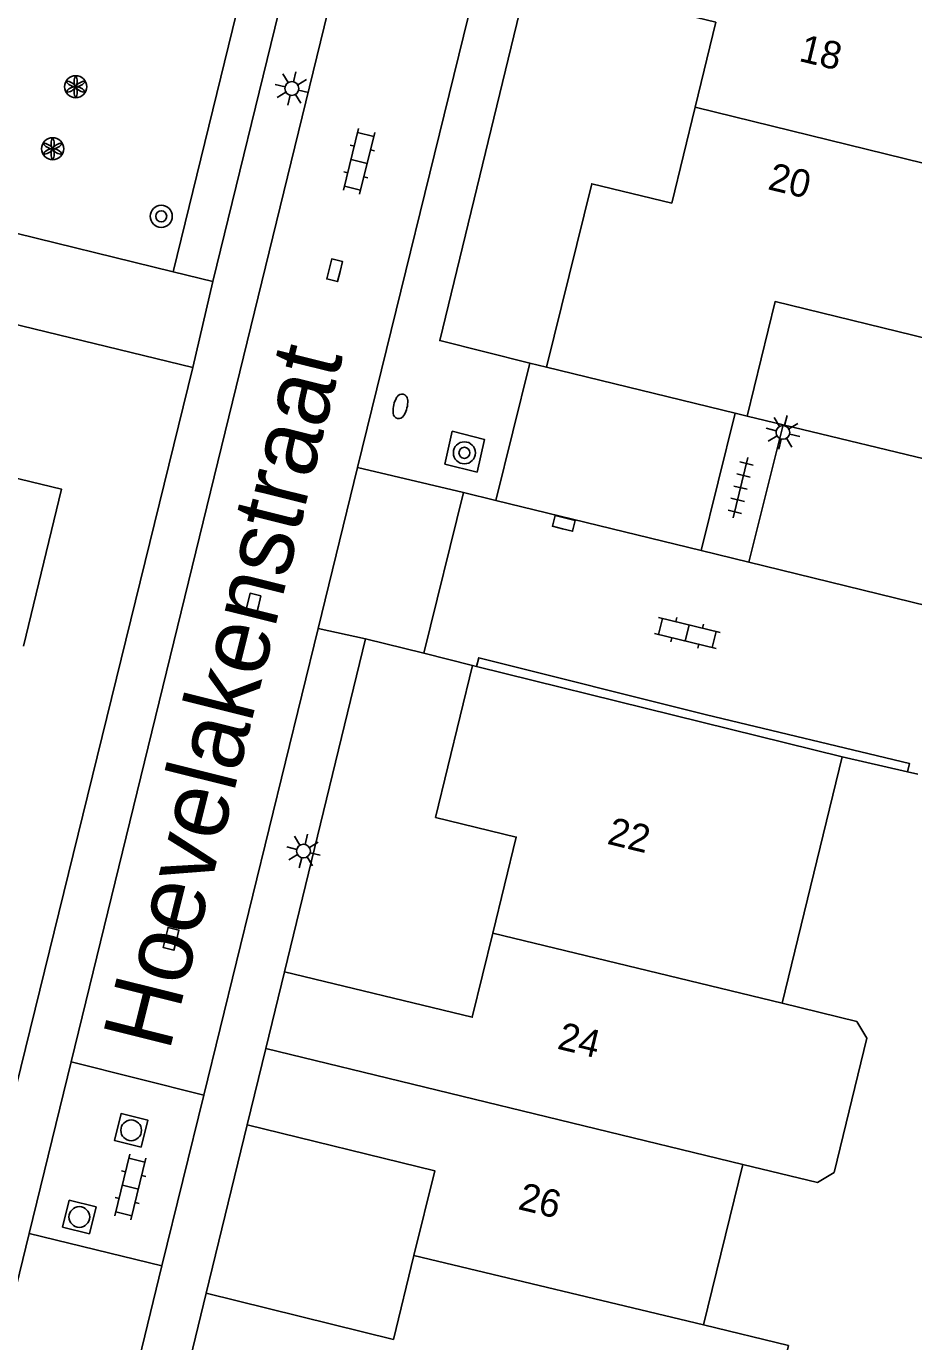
# Model space of a CAD drawing. Extents: x 128000 to 131008, y 398996 to 402500.
# Drawn here: x 128188.47 to 128220.62, y 399514.1 to 399561.75 of the extents above; entities that cross this region are included whole.
import ezdxf

# ---------------------------------------------------------------- set-up
doc = ezdxf.new("R2010")
doc.units = 0
for name, color, linetype in [('gg-afsc-hekwerk', 7, 'Continuous'), ('gg-afsc-muur', 7, 'Continuous'), ('gg-anno-huisnummerreeks BGT', 7, 'Continuous'), ('gg-anno-openbare ruimte label', 7, 'Continuous'), ('gg-bbg-gedigitaliseerde bebouwing', 7, 'Continuous'), ('gg-bbg-hoofdgebouw', 7, 'Continuous'), ('gg-bbg-tussenscheiding', 7, 'Continuous'), ('gg-knt-verharding', 7, 'Continuous'), ('gg-knt-verharding nz', 7, 'Continuous'), ('gt-grn-weggrens', 7, 'Continuous'), ('gt-symb-boom', 7, 'Continuous'), ('gt-symb-brandkraan', 7, 'Continuous'), ('gt-symb-klinker verharding', 7, 'Continuous'), ('gt-symb-kolk', 7, 'Continuous'), ('gt-symb-lichtmast', 7, 'Continuous'), ('gt-symb-rioolschacht', 7, 'Continuous'), ('gt-symb-solitaire heester', 7, 'Continuous'), ('gt-symb-tegel verharding', 7, 'Continuous')]:
    doc.layers.add(name, color=color, linetype=linetype)

# ---------------------------------------------------------------- blocks, each defined once
blk = doc.blocks.new('gt0-KOLK')
at = {"layer": 'gt-symb-kolk'}
blk.add_lwpolyline([(0, 0), (0.375, 0), (0.375, 0.4), (-0.375, 0.4), (-0.375, 0), (0, 0)], dxfattribs=at)
blk = doc.blocks.new('gt0-TEG1')
at = {"layer": 'gt-symb-tegel verharding'}
for p, q in [((-1.125, 0), (1.125, 0)), ((-0.9, -0.25), (-0.9, 0.25)), ((-0.45, -0.25), (-0.45, 0.25)), ((0, -0.25), (0, 0.25)), ((0.45, -0.25), (0.45, 0.25)), ((0.9, -0.25), (0.9, 0.25))]:
    blk.add_line(p, q, dxfattribs=at)
blk = doc.blocks.new('gt0-LMAST')
at = {"layer": 'gt-symb-lichtmast'}
for p, q in [((-0.005, 0.246), (-0.005, 0.621)), ((-0.182, 0.173), (-0.447, 0.438)), ((0.172, 0.173), (0.437, 0.438)), ((-0.255, -0.004), (-0.63, -0.004)), ((-0.182, -0.181), (-0.447, -0.446)), ((-0.005, -0.254), (-0.005, -0.629)), ((0.437, -0.446), (0.172, -0.181)), ((0.245, -0.004), (0.62, -0.004))]:
    blk.add_line(p, q, dxfattribs=at)
blk.add_circle((-0.005, -0.004), 0.25, dxfattribs=at)
blk = doc.blocks.new('gt0-KL1')
at = {"layer": 'gt-symb-klinker verharding'}
for p, q in [((-1.15, 0.3), (1.15, 0.3)), ((-1, -0.3), (-1, 0.3)), ((-0.5, 0.3), (-0.5, 0.45)), ((0, -0.3), (0, 0.3)), ((0.5, 0.3), (0.5, 0.45)), ((1, -0.3), (1, 0.3)), ((-1.15, -0.3), (1.15, -0.3)), ((-0.5, -0.45), (-0.5, -0.3)), ((0.5, -0.45), (0.5, -0.3))]:
    blk.add_line(p, q, dxfattribs=at)
blk = doc.blocks.new('gt0-BR')
at = {"layer": 'gt-symb-brandkraan'}
for centre, radius, start, end in [((-0.244, 0), 0.206, 107.5669, 252.4331), ((0.599, -2.664), 3, 106.892, 107.5669), ((0, -0.691), 0.938, 73.108, 106.892), ((-0.599, -2.664), 3, 72.4331, 73.108), ((0.244, 0), 0.206, 287.567, 72.4331), ((0.599, 2.664), 3, 252.4331, 253.108), ((0, 0.691), 0.938, 253.108, 286.8921), ((-0.599, 2.664), 3, 286.8921, 287.567)]:
    blk.add_arc(centre, radius, start, end, dxfattribs=at)
blk = doc.blocks.new('gt0-BOOM')
at = {"layer": 'gt-symb-boom'}
for radius in [0.4, 0.2]:
    blk.add_circle((0, 0), radius, dxfattribs=at)
blk = doc.blocks.new('gt0-SH')
at = {"layer": 'gt-symb-solitaire heester'}
blk.add_circle((0, 0), 0.4, dxfattribs=at)
for centre, start, end in [((-0.346, 0.2), 270, 30), ((-0.346, -0.2), 330, 90), ((0, 0.4), 210, 330), ((0.346, 0.2), 150, 270), ((0.346, -0.2), 90, 210), ((0, -0.4), 30, 150)]:
    blk.add_arc(centre, 0.4, start, end, dxfattribs=at)
blk = doc.blocks.new('gt0-RS')
at = {"layer": 'gt-symb-rioolschacht'}
blk.add_lwpolyline([(-0.5, -0.5), (0.5, -0.5), (0.5, 0.5), (-0.5, 0.5)], close=True, dxfattribs=at)
blk.add_circle((0, 0), 0.375, dxfattribs=at)

msp = doc.modelspace()

# ---------------------------------------------------------------- linework, layer by layer
at = {"layer": 'gg-afsc-hekwerk'}
for p, q in [((128203.453, 399592.417), (128193.793, 399552.859)), ((128193.793, 399552.859), (128181.326, 399555.921))]:
    msp.add_line(p, q, dxfattribs=at)
at = {"layer": 'gg-afsc-muur'}
for p, q in [((128218.032, 399535.289), (128220.403, 399534.741)), ((128220.403, 399534.741), (128220.773, 399534.656))]:
    msp.add_line(p, q, dxfattribs=at)
at = {"layer": 'gg-bbg-gedigitaliseerde bebouwing'}
for p, q in [((128218.032, 399535.289), (128215.854, 399526.359)), ((128214.43, 399520.521), (128213.012, 399514.704))]:
    msp.add_line(p, q, dxfattribs=at)
for points in [[(128215.854, 399526.359), (128218.56, 399525.702), (128218.927, 399525.098), (128217.745, 399520.231), (128217.141, 399519.863), (128214.43, 399520.521)], [(128213.012, 399514.704), (128216.086, 399513.957), (128214.667, 399508.119), (128211.588, 399508.867)]]:
    msp.add_lwpolyline(points, dxfattribs=at)
at = {"layer": 'gg-bbg-hoofdgebouw'}
for p, q in [((128207.32, 399549.4), (128214.161, 399547.735)), ((128214.161, 399547.735), (128214.591, 399547.63)), ((128204.787, 399538.564), (128204.64, 399538.6)), ((128211.92, 399536.8), (128204.787, 399538.564)), ((128211.92, 399536.8), (128218.032, 399535.289)), ((128197.83, 399527.501), (128197.149, 399524.722)), ((128197.149, 399524.722), (128196.47, 399521.95)), ((128194.99, 399515.85), (128194.305, 399513.065))]:
    msp.add_line(p, q, dxfattribs=at)
for points in [[(128212.703, 399558.823), (128213.45, 399561.9), (128206.66, 399563.56)], [(128207.32, 399549.4), (128208.96, 399556.05), (128211.86, 399555.35), (128212.703, 399558.823)], [(128223.189, 399556.244), (128221.73, 399550.281), (128215.6, 399551.78), (128214.591, 399547.63)], [(128188.367, 399539.296), (128189.75, 399544.98), (128185.992, 399545.895)], [(128204.64, 399538.6), (128203.3, 399533.09), (128206.22, 399532.38), (128205.374, 399528.904)], [(128205.374, 399528.904), (128204.63, 399525.85), (128197.83, 399527.501)], [(128196.47, 399521.95), (128203.27, 399520.29), (128202.517, 399517.224)], [(128202.517, 399517.224), (128201.77, 399514.181), (128194.99, 399515.85)]]:
    msp.add_lwpolyline(points, dxfattribs=at)
at = {"layer": 'gg-bbg-tussenscheiding'}
for p, q in [((128212.703, 399558.823), (128223.189, 399556.244)), ((128205.374, 399528.904), (128215.854, 399526.359)), ((128197.149, 399524.722), (128214.43, 399520.521)), ((128202.517, 399517.224), (128213.012, 399514.704))]:
    msp.add_line(p, q, dxfattribs=at)
at = {"layer": 'gg-knt-verharding'}
for p, q in [((128205.008, 399592.472), (128195.231, 399552.506)), ((128190.091, 399524.233), (128201.678, 399571.644)), ((128200.476, 399545.767), (128206.527, 399570.454)), ((128195.231, 399552.506), (128193.793, 399552.859)), ((128194.5, 399549.39), (128185.888, 399551.491)), ((128194.5, 399549.39), (128176.7, 399476.98)), ((128205.486, 399544.573), (128206.715, 399549.552)), ((128206.715, 399549.552), (128207.32, 399549.4)), ((128214.161, 399547.735), (128212.919, 399542.758)), ((128215.897, 399547.315), (128214.591, 399547.63)), ((128214.656, 399542.334), (128215.897, 399547.315)), ((128223.442, 399545.498), (128215.897, 399547.315)), ((128199.046, 399539.934), (128200.476, 399545.767)), ((128202.87, 399539.038), (128204.31, 399544.86)), ((128204.31, 399544.86), (128205.486, 399544.573)), ((128212.919, 399542.758), (128214.656, 399542.334)), ((128194.901, 399523.025), (128199.046, 399539.934)), ((128200.76, 399539.56), (128197.83, 399527.501)), ((128202.87, 399539.038), (128200.76, 399539.56)), ((128204.64, 399538.6), (128202.87, 399539.038)), ((128188.573, 399518.02), (128190.091, 399524.233)), ((128190.091, 399524.233), (128194.901, 399523.025)), ((128193.385, 399516.842), (128194.901, 399523.025)), ((128196.47, 399521.95), (128194.99, 399515.85)), ((128178.59, 399477.177), (128188.573, 399518.02)), ((128193.385, 399516.842), (128188.573, 399518.02)), ((128183.37, 399475.983), (128193.385, 399516.842))]:
    msp.add_line(p, q, dxfattribs=at)
for points in [[(128206.66, 399563.56), (128203.45, 399550.37), (128206.715, 399549.552)], [(128204.801, 399545.606), (128203.636, 399545.896), (128203.901, 399547.084), (128205.07, 399546.788), (128204.801, 399545.606)], [(128220.403, 399534.741), (128220.475, 399535.04), (128213.115, 399536.811), (128204.865, 399538.876), (128204.787, 399538.564)]]:
    msp.add_lwpolyline(points, dxfattribs=at)
at = {"layer": 'gg-knt-verharding nz'}
for p, q in [((128205.486, 399544.573), (128212.919, 399542.758)), ((128214.656, 399542.334), (128222.199, 399540.493))]:
    msp.add_line(p, q, dxfattribs=at)
at = {"layer": 'gt-grn-weggrens'}
for p, q in [((128195.231, 399552.506), (128194.5, 399549.39)), ((128200.476, 399545.767), (128204.31, 399544.86)), ((128200.76, 399539.56), (128199.046, 399539.934))]:
    msp.add_line(p, q, dxfattribs=at)

# ---------------------------------------------------------------- block references
at = {"layer": 'gt-symb-boom', "rotation": -13.716469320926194}
msp.add_blockref('gt0-BOOM', (128193.358, 399554.87), dxfattribs=at)
at = {"layer": 'gt-symb-boom'}
msp.add_blockref('gt0-BOOM', (128204.345, 399546.301), dxfattribs=at)
at = {"layer": 'gt-symb-brandkraan', "rotation": 76.22785456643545}
msp.add_blockref('gt0-BR', (128202.024, 399547.986), dxfattribs=at)
at = {"layer": 'gt-symb-klinker verharding'}
for p, rotation in [((128200.529, 399556.859), 76.28353067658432), ((128212.419, 399539.774), -13.71646932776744), ((128192.242, 399519.698), 76.2835306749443)]:
    msp.add_blockref('gt0-KL1', p, dxfattribs=dict(at, rotation=rotation))
at = {"layer": 'gt-symb-kolk'}
for p, rotation in [((128199.837, 399552.869), 76.22785456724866), ((128207.9, 399543.551), -13.71646932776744), ((128196.878, 399540.751), 76.22785456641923), ((128193.908, 399528.645), 76.22785456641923)]:
    msp.add_blockref('gt0-KOLK', p, dxfattribs=dict(at, rotation=rotation))
at = {"layer": 'gt-symb-lichtmast'}
for p, rotation in [((128198.09, 399559.505), 76.22785456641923), ((128215.893, 399547.045), -13.716469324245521), ((128198.509, 399531.879), 76.22785456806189)]:
    msp.add_blockref('gt0-LMAST', p, dxfattribs=dict(at, rotation=rotation))
at = {"layer": 'gt-symb-rioolschacht'}
for p, rotation in [((128192.27, 399521.755), 76.17220496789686), ((128190.392, 399518.615), 76.17220496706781)]:
    msp.add_blockref('gt0-RS', p, dxfattribs=dict(at, rotation=rotation))
at = {"layer": 'gt-symb-solitaire heester'}
for p in [(128190.26, 399559.565), (128189.424, 399557.317)]:
    msp.add_blockref('gt0-SH', p, dxfattribs=at)
at = {"layer": 'gt-symb-tegel verharding', "rotation": 76.28353067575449}
msp.add_blockref('gt0-TEG1', (128214.352, 399545.038), dxfattribs=at)

# ---------------------------------------------------------------- texts
at = {"layer": 'gg-anno-huisnummerreeks BGT'}
for s, rotation, p in [('18', 346.4, (128216.428, 399560.504)), ('20', 346.4, (128215.3, 399555.857)), ('22', 346.3, (128209.48, 399532.143)), ('24', 346.3, (128207.672, 399524.719)), ('26', 346.2, (128206.248, 399518.908))]:
    msp.add_text(s, height=1, rotation=rotation, dxfattribs=at).set_placement(p)
at = {"layer": 'gg-anno-openbare ruimte label'}
msp.add_text('Hoevelakenstraat', height=2.5, rotation=76, dxfattribs=at).set_placement((128193.647, 399524.575))

doc.saveas('drawing.dxf')
